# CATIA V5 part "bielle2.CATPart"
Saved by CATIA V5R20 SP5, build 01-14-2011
Part number: bielle2
Bounding box of the stored display mesh (mm): x -412.981 to -324.336, y -27.61 to -21, z -154.611 to -104.698
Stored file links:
  F:\iao\catia\projet iao\bielle2.CATPart
  F:\iao\catia\projet iao\fhartmann.CATProduct
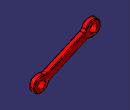
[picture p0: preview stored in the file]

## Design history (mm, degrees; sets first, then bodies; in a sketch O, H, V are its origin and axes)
External parameters (linked from other documents)
  External.bielle_longueur = 75 mm
  External.bielle1_epaisseur = 6.61 mm
  External.bielle_diametre_ext = 20 mm
  External.bielle_diametre_int = 10 mm
Set1
  Plane1: linked copy from another document
  Point1: linked copy from another document
  Point2: linked copy from another document
  Plane2: linked copy from another document
  Point3: linked copy from another document
Body1 (main body)
  Sketch1 on Plane1, origin (-299.709, 230.7285, 28.0171), H (0, 1, 0), V (0.4007, 0, 0.9162)
    line L1 (-251.7285, -177.1534) -> (-258.3385, -177.1534)
    line L2 (-258.3385, -177.1534) -> (-258.3385, -167.1534)
    line L3 (-258.3385, -167.1534) -> (-251.7285, -167.1534)
    line L4 (-251.7285, -167.1534) -> (-251.7285, -177.1534)
    point P2 (-258.3385, -177.1534)
    point P4 (-251.7285, -167.1534)
    reference projected point E1 (-258.3385, -177.1534) from Point1
    reference projected point E2 (-251.7285, -167.1534) from Point2
    distance L2 L4 = 6.61 {= External.bielle1_epaisseur}
    parallelism: L1 L3
    perpendicularity: L1 L4
    coincidence: P2 E1, P4 E2
  Pad1: profile Sketch1, direction (0.9162, 0, -0.4007), length 37.5 {= External.bielle_longueur /2}, opposite side length 37.5 {= External.bielle_longueur /2}
  Sketch2 on Plane2, origin (-23.5, -24.305, 0), H (-1, 0, 0), V (0, 0, 1)
    circle A1 centre (310.8365, -144.7371) radius 10
    point P1 (310.8365, -144.7371)
    reference projected point E1 (310.8365, -144.7371) from Point3
    radius A1 = 10 {= External.bielle_diametre_ext /2}
    coincidence: P1 E1
  Pad2: profile Sketch2, direction (0, 1, 0), length 3.305 {= External.bielle1_epaisseur /2}, opposite side length 3.305 {= External.bielle1_epaisseur /2}
  Sketch3 on face of Pad2, origin (-103.5, -27.61, 0), H (-1, 0, 0), V (0, 0, -1)
    point P1 (230.8365, 144.7371)
    reference projected point E1 (230.8365, 144.7371) from Point3
    coincidence: E1 P1
  Hole1: placed by Sketch3, at (-334.3365, -27.61, -144.7371) direction (0, 1, 0), diameter 10 {= External.bielle_diametre_int}, depth 6.61 {= External.bielle1_epaisseur}
  Fillet1: radius 5, on edge [face of Pad2 from Sketch2.A1 | face of Pad1 from Sketch1.L1]; edge [face of Pad1 from Sketch1.L3 | face of Pad2 from Sketch2.A1]
  Mirror1: of Pad2, Hole1, about Plane1
  Fillet2: radius 5, on edge [face of Mirror1 | face of Pad1 from Sketch1.L3]; edge [face of Pad1 from Sketch1.L1 | face of Mirror1]
  Chamfer1: length 1, angle 45, on edge [face of Mirror1 | face of Mirror1] (x2)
